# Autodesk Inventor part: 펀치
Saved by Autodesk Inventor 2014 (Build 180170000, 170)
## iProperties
Created: 2024-08
Part Number: 펀치
Material: 일반
Document SubType Name: Modeling
Designer: dg
Density: 1 g/cm^3
Appearance: 기본값
Author: dg
Author: jhkim
Creation Date: 2024-08-09
Sending System: Autodesk Inventor 2025
Preprocessor: ST-DEVELOPER v20
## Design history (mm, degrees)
node "펀치1"
node "솔리드1"
node "기준1"
